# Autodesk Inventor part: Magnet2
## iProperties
Created: 2007-01
Part Number: Magnet2
Cost Center: 0 kg
Material: S235JRG2 (1.0038)
Document SubType Name: Modeling
Designer: M. Fiedler
Manufacturer: Standard
Standards Organization: Custom
Author: M. Fiedler
Einheit: Stück
Ersatzteil: ET AB VT
Grundoberfläche: Rz6.3
WSK a+: 0
WSK a-: -0.1
WSK i+: +0.1
WSK i-: 0
SaveDate: 2007-01-25
SaveTime: 20:47
Masse: 0 kg
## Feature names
1. Drehung1 [Revolution]
2. Abgeleiteter Körper1 [Tagging]
